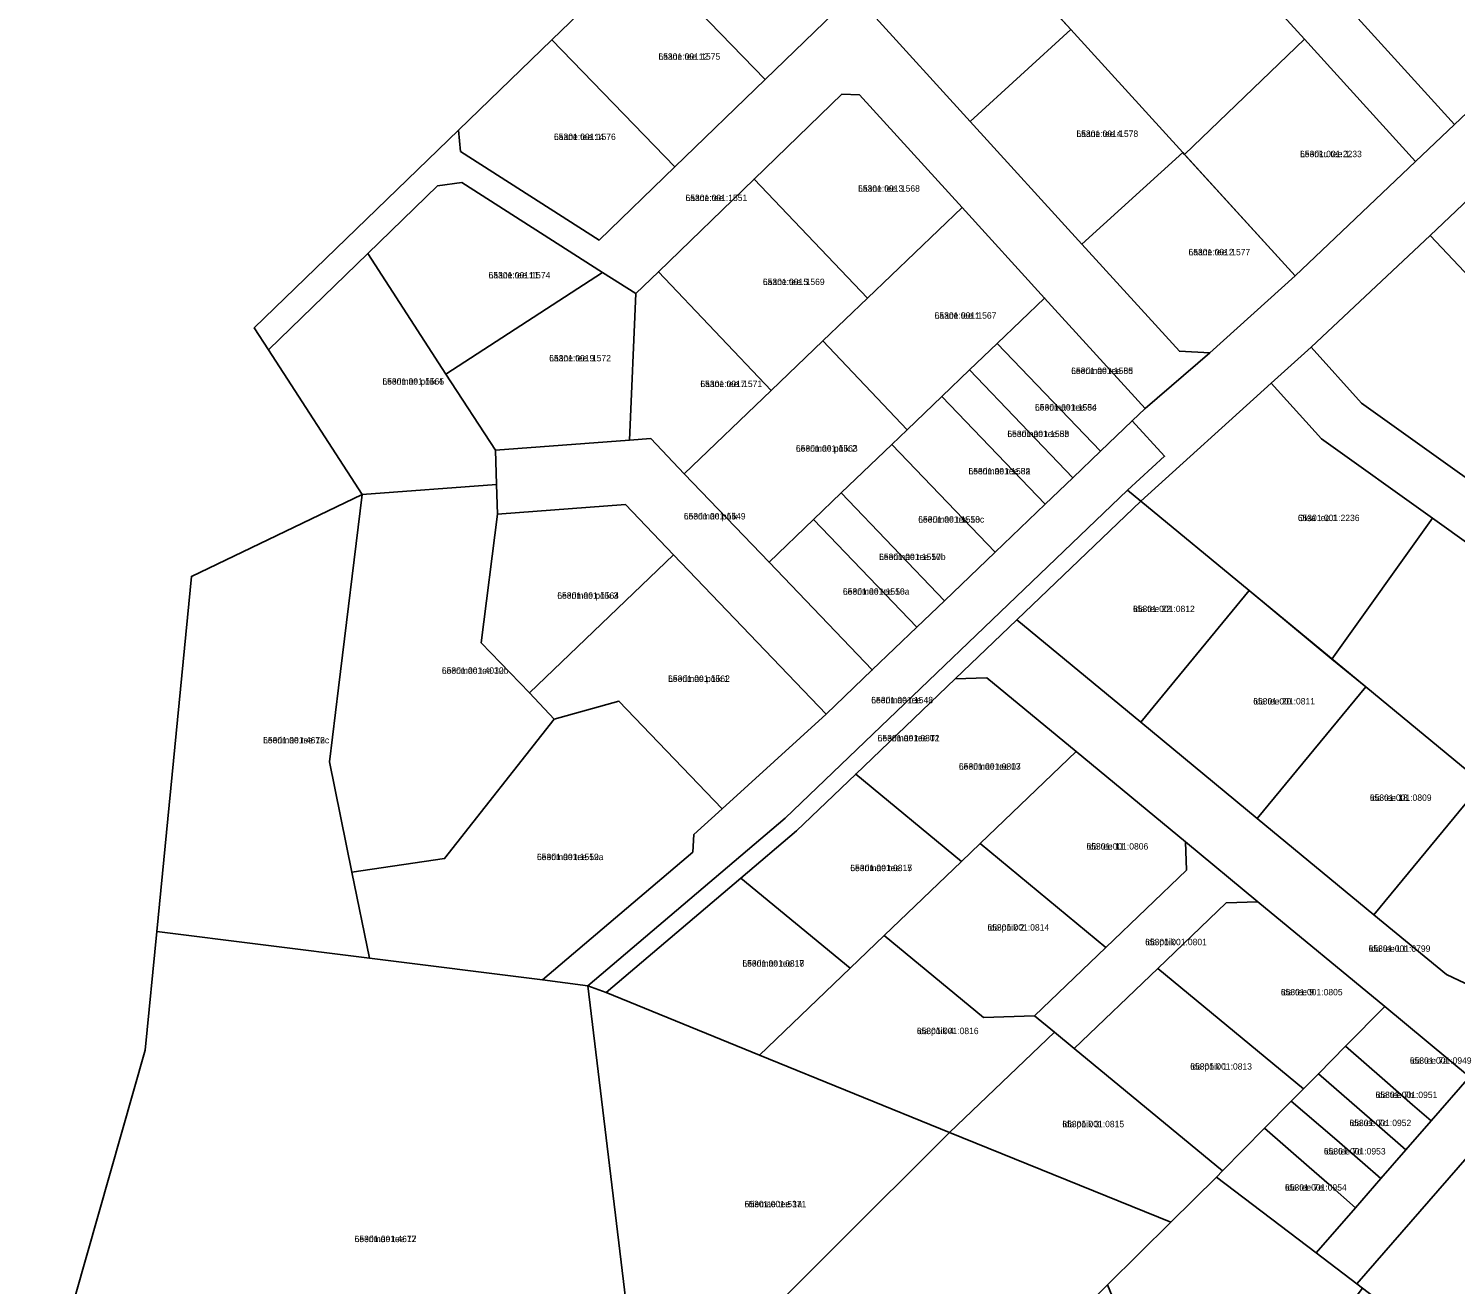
# Model space of a CAD drawing. Extents: x 543236 to 563717, y 6566033 to 6588992.
# Drawn here: x 544925.3 to 545260.3, y 6583719.4 to 6584014.2 of the extents above; entities that cross this region are included whole.
import ezdxf

# ---------------------------------------------------------------- set-up
doc = ezdxf.new("R2010")
doc.units = 0
for name, color, linetype in [('L_AADRESS', 7, 'Continuous'), ('PIIR', 7, 'Continuous'), ('TUNNUS', 7, 'Continuous')]:
    doc.layers.add(name, color=color, linetype=linetype)

msp = doc.modelspace()

# ---------------------------------------------------------------- linework, layer by layer
at = {"layer": 'PIIR'}
for points in [[(545178.33, 6584081.44), (545187.09, 6584071.83), (545210.66, 6584045.94), (545234.23, 6584020.06), (545260.06, 6583991.69), (545250.92, 6583983.02), (545224.81, 6584011.69), (545195.17, 6584044.24), (545169.24, 6584072.71), (545173.77, 6584077.07)], [(545184.39, 6583922.14), (545187.41, 6583925.03), (545202.59, 6583938.1), (545222.62, 6583956.17), (545250.92, 6583983.02), (545260.06, 6583991.69), (545293.45, 6584023.35), (545302.59, 6584032.02), (545335.77, 6584063.49), (545347.4, 6584053.85), (545312.69, 6584020.93), (545303.56, 6584012.25), (545263.51, 6583974.28), (545254.34, 6583965.59), (545226.41, 6583939.39), (545217.05, 6583930.95), (545186.41, 6583903.29), (545183.3, 6583905.86), (545191.99, 6583913.79)], [(545069.35, 6584032.04), (545077.3, 6584039.73), (545091.09, 6584053.08), (545119.05, 6584022.38), (545098.21, 6584002.21)], [(545293.45, 6584023.35), (545260.06, 6583991.69), (545234.23, 6584020.06), (545267.42, 6584051.94)], [(545139.7, 6584047.23), (545170, 6584013.95), (545146.34, 6583992.4), (545123.42, 6584017.57)], [(545167.04, 6584017.21), (545195.17, 6584044.24), (545224.81, 6584011.69), (545196.67, 6583984.66), (545196.26, 6583985.12), (545170, 6584013.95)], [(545048.15, 6584011.52), (545069.35, 6584032.04), (545098.21, 6584002.21), (545077.01, 6583981.7)], [(545307.09, 6583923.8), (545266.41, 6583952.86), (545254.34, 6583965.59), (545263.51, 6583974.28), (545274.79, 6583962.43), (545275.28, 6583962.08), (545307.39, 6583939.01), (545356.24, 6583904.18), (545380.64, 6583938.37), (545371.66, 6583954.62), (545340.53, 6583976.87), (545336.5, 6583979.74), (545314.08, 6583995.73), (545310.09, 6584002.03), (545303.56, 6584012.25), (545312.69, 6584020.93), (545322.94, 6584004.89), (545381.28, 6583963.21), (545395.56, 6583937.53), (545359.17, 6583886.59)], [(545026.21, 6583990.3), (545048.15, 6584011.52), (545077.01, 6583981.7), (545059.28, 6583964.55), (545026.71, 6583985.34)], [(545170, 6584013.95), (545196.26, 6583985.12), (545172.6, 6583963.57), (545146.34, 6583992.4)], [(545224.81, 6584011.69), (545250.92, 6583983.02), (545222.62, 6583956.17), (545196.67, 6583984.66)], [(545095.63, 6583978.85), (545116.21, 6583998.76), (545120.39, 6583998.63), (545144.47, 6583972.18), (545122.23, 6583950.88)], [(545196.26, 6583985.12), (545222.62, 6583956.17), (545202.59, 6583938.1), (545195.5, 6583938.43), (545172.6, 6583963.57)], [(545004.94, 6583961.37), (545021.35, 6583977.25), (545027.04, 6583978.02), (545060.05, 6583956.94), (545023.29, 6583933.09)], [(545073.18, 6583957.12), (545095.63, 6583978.85), (545122.23, 6583950.88), (545111.77, 6583940.86), (545099.66, 6583929.26)], [(545111.77, 6583940.86), (545122.23, 6583950.88), (545144.47, 6583972.18), (545163.83, 6583950.92), (545152.73, 6583940.28), (545146.23, 6583934.06), (545139.73, 6583927.83), (545131.58, 6583920.02)], [(545226.41, 6583939.39), (545254.34, 6583965.59), (545266.41, 6583952.86), (545307.09, 6583923.8), (545285, 6583892.88), (545238.22, 6583926.3)], [(544981.62, 6583938.8), (545004.94, 6583961.37), (545023.29, 6583933.09), (545034.91, 6583915.2), (545035.15, 6583907.17), (545003.65, 6583904.82)], [(545067.85, 6583951.97), (545073.18, 6583957.12), (545099.66, 6583929.26), (545079.25, 6583909.71), (545071.36, 6583917.94), (545066.38, 6583917.57)], [(545023.29, 6583933.09), (545060.05, 6583956.94), (545067.85, 6583951.97), (545066.38, 6583917.57), (545034.91, 6583915.2)], [(545152.73, 6583940.28), (545163.83, 6583950.92), (545187.41, 6583925.03), (545184.39, 6583922.14), (545176.94, 6583915)], [(545079.25, 6583909.71), (545099.66, 6583929.26), (545111.77, 6583940.86), (545131.58, 6583920.02), (545127.97, 6583916.56), (545116.11, 6583905.2), (545109.61, 6583898.97), (545099.14, 6583888.94)], [(545146.23, 6583934.06), (545152.73, 6583940.28), (545176.94, 6583915), (545170.45, 6583908.77)], [(545217.05, 6583930.95), (545226.41, 6583939.39), (545238.22, 6583926.3), (545285, 6583892.88), (545337.08, 6583855.67), (545339.23, 6583858.68), (545345.74, 6583854.03), (545324.81, 6583824.73), (545318.3, 6583829.38), (545329.93, 6583845.66), (545292.33, 6583872.52), (545254.9, 6583899.25), (545228.87, 6583917.86)], [(545139.73, 6583927.83), (545146.23, 6583934.06), (545170.45, 6583908.77), (545163.95, 6583902.54)], [(545231.3, 6583866.21), (545211.86, 6583882.26), (545186.41, 6583903.29), (545217.05, 6583930.95), (545228.87, 6583917.86), (545254.9, 6583899.25)], [(545127.97, 6583916.56), (545131.58, 6583920.02), (545139.73, 6583927.83), (545163.95, 6583902.54), (545152.2, 6583891.27)], [(545045.98, 6583790.92), (545081.22, 6583820.91), (545081.46, 6583824.99), (545088.12, 6583831.05), (545112.55, 6583853.26), (545123.38, 6583863.64), (545133.84, 6583873.67), (545140.34, 6583879.9), (545152.2, 6583891.27), (545163.95, 6583902.54), (545170.45, 6583908.77), (545176.94, 6583915), (545184.39, 6583922.14), (545191.99, 6583913.79), (545183.3, 6583905.86), (545102.91, 6583828.86), (545056.58, 6583789.51)], [(545034.91, 6583915.2), (545066.38, 6583917.57), (545071.36, 6583917.94), (545079.25, 6583909.71), (545099.14, 6583888.94), (545123.38, 6583863.64), (545112.55, 6583853.26), (545076.73, 6583890.65), (545065.43, 6583902.45), (545035.39, 6583900.19), (545035.15, 6583907.17)], [(545116.11, 6583905.2), (545127.97, 6583916.56), (545152.2, 6583891.27), (545140.34, 6583879.9)], [(544998.1, 6583859.46), (545003.65, 6583904.82), (545035.15, 6583907.17), (545035.39, 6583900.19), (545031.59, 6583870.03), (545042.91, 6583858.26), (545048.74, 6583852.1), (545022.99, 6583819.39), (545001.22, 6583816.2), (544995.93, 6583842.09)], [(544955.42, 6583802.27), (544963.54, 6583885.61), (545003.65, 6583904.82), (544998.1, 6583859.46), (544995.93, 6583842.09), (545001.22, 6583816.2), (545005.34, 6583796.01)], [(545056.58, 6583789.51), (545102.91, 6583828.86), (545183.3, 6583905.86), (545186.41, 6583903.29), (545157.32, 6583875.44), (545142.8, 6583861.53), (545119.51, 6583839.22), (545105.59, 6583825.89), (545092.55, 6583814.8), (545060.94, 6583787.95)], [(545109.61, 6583898.97), (545116.11, 6583905.2), (545140.34, 6583879.9), (545133.84, 6583873.67)], [(545035.39, 6583900.19), (545065.43, 6583902.45), (545076.73, 6583890.65), (545042.91, 6583858.26), (545031.59, 6583870.03)], [(545186.41, 6583903.29), (545211.86, 6583882.26), (545186.39, 6583851.42), (545157.32, 6583875.44)], [(545099.14, 6583888.94), (545109.61, 6583898.97), (545133.84, 6583873.67), (545123.38, 6583863.64)], [(545231.3, 6583866.21), (545254.9, 6583899.25), (545292.33, 6583872.52), (545266.84, 6583836.84), (545266.6, 6583837.04), (545239.23, 6583859.65)], [(545042.91, 6583858.26), (545076.73, 6583890.65), (545112.55, 6583853.26), (545088.12, 6583831.05), (545063.91, 6583856.32), (545048.74, 6583852.1)], [(545211.86, 6583882.26), (545239.23, 6583859.65), (545213.76, 6583828.81), (545186.39, 6583851.42)], [(545142.8, 6583861.53), (545157.32, 6583875.44), (545186.39, 6583851.42), (545213.76, 6583828.81), (545241.12, 6583806.2), (545258.15, 6583792.14), (545284.32, 6583779.8), (545285.35, 6583762.76), (545277.86, 6583766.26), (545237.13, 6583719.53), (545227.55, 6583726.81), (545236.8, 6583737.42), (545242.8, 6583744.3), (545248.66, 6583751.03), (545254.56, 6583757.79), (545263.61, 6583768.17), (545243.69, 6583784.63), (545213.92, 6583809.22), (545196.89, 6583823.29), (545171.25, 6583844.47), (545150.27, 6583861.81)], [(545142.8, 6583861.53), (545150.27, 6583861.81), (545171.25, 6583844.47), (545148.71, 6583822.88), (545144.35, 6583818.7), (545119.51, 6583839.22)], [(545239.23, 6583859.65), (545266.6, 6583837.04), (545241.12, 6583806.2), (545213.76, 6583828.81)], [(545001.22, 6583816.2), (545022.99, 6583819.39), (545048.74, 6583852.1), (545063.91, 6583856.32), (545088.12, 6583831.05), (545081.46, 6583824.99), (545081.22, 6583820.91), (545045.98, 6583790.92), (545005.34, 6583796.01)], [(545148.71, 6583822.88), (545171.25, 6583844.47), (545196.89, 6583823.29), (545197.14, 6583816.65), (545178.21, 6583798.52)], [(545092.55, 6583814.8), (545105.59, 6583825.89), (545119.51, 6583839.22), (545144.35, 6583818.7), (545126.17, 6583801.29), (545118.17, 6583793.63)], [(545266.6, 6583837.04), (545266.84, 6583836.84), (545281.6, 6583824.65), (545284.32, 6583779.8), (545258.15, 6583792.14), (545241.12, 6583806.2)], [(545161.48, 6583782.5), (545178.21, 6583798.52), (545197.14, 6583816.65), (545196.89, 6583823.29), (545213.92, 6583809.22), (545206.45, 6583808.95), (545190.43, 6583793.61), (545170.8, 6583774.8), (545166.14, 6583778.65)], [(545126.17, 6583801.29), (545144.35, 6583818.7), (545148.71, 6583822.88), (545178.21, 6583798.52), (545161.48, 6583782.5), (545149.46, 6583782.06)], [(545060.94, 6583787.95), (545092.55, 6583814.8), (545118.17, 6583793.63), (545096.89, 6583773.25)], [(545190.43, 6583793.61), (545206.45, 6583808.95), (545213.92, 6583809.22), (545243.69, 6583784.63), (545234.5, 6583775.32), (545228.11, 6583768.86), (545224.64, 6583765.34)], [(544952.71, 6583774.41), (544955.42, 6583802.27), (545005.34, 6583796.01), (545045.98, 6583790.92), (545056.58, 6583789.51), (545067.62, 6583698.06), (545018.53, 6583682.88), (544931.46, 6583656.42), (544925.31, 6583678.14)], [(545096.89, 6583773.25), (545118.17, 6583793.63), (545126.17, 6583801.29), (545149.46, 6583782.06), (545161.48, 6583782.5), (545166.14, 6583778.65), (545141.51, 6583755.06)], [(545170.8, 6583774.8), (545190.43, 6583793.61), (545224.64, 6583765.34), (545221.75, 6583762.42), (545215.48, 6583756.07), (545205.59, 6583746.06)], [(545141.51, 6583755.06), (545087.4, 6583701.18), (545071.7, 6583685.58), (545067.62, 6583698.06), (545056.58, 6583789.51), (545060.94, 6583787.95), (545096.89, 6583773.25)], [(545234.5, 6583775.32), (545243.69, 6583784.63), (545263.61, 6583768.17), (545254.56, 6583757.79), (545250.22, 6583761.58), (545243.68, 6583767.3)], [(545141.51, 6583755.06), (545166.14, 6583778.65), (545170.8, 6583774.8), (545205.59, 6583746.06), (545204.16, 6583744.59), (545193.44, 6583734)], [(545228.11, 6583768.86), (545234.5, 6583775.32), (545243.68, 6583767.3), (545250.22, 6583761.58), (545254.56, 6583757.79), (545248.66, 6583751.03), (545242.43, 6583756.43), (545237.75, 6583760.5)], [(545221.75, 6583762.42), (545224.64, 6583765.34), (545228.11, 6583768.86), (545237.75, 6583760.5), (545242.43, 6583756.43), (545248.66, 6583751.03), (545242.8, 6583744.3), (545238.45, 6583748.05), (545231.86, 6583753.72)], [(545277.86, 6583766.26), (545285.35, 6583762.76), (545286.89, 6583737.31), (545280.75, 6583729.02), (545260.51, 6583701.71), (545238.43, 6583718.54), (545237.13, 6583719.53)], [(545215.48, 6583756.07), (545221.75, 6583762.42), (545231.86, 6583753.72), (545238.45, 6583748.05), (545242.8, 6583744.3), (545236.8, 6583737.42), (545230.61, 6583742.84), (545225.94, 6583746.92)], [(545124.68, 6583665.46), (545097.13, 6583638.45), (545083.06, 6583683.22), (545089.67, 6583693.89), (545087.4, 6583701.18), (545141.51, 6583755.06), (545193.44, 6583734), (545178.62, 6583719.3), (545143.81, 6583684.42)], [(545204.16, 6583744.59), (545205.59, 6583746.06), (545215.48, 6583756.07), (545225.94, 6583746.92), (545230.61, 6583742.84), (545236.8, 6583737.42), (545227.55, 6583726.81)], [(545204.16, 6583744.59), (545227.55, 6583726.81), (545237.13, 6583719.53), (545238.43, 6583718.54), (545206.42, 6583676.48), (545191.67, 6583687.57), (545178.62, 6583719.3), (545193.44, 6583734)]]:
    msp.add_lwpolyline(points, close=True, dxfattribs=at)
msp.add_lwpolyline([(545123.42, 6584017.57), (545146.34, 6583992.4), (545172.6, 6583963.57), (545195.5, 6583938.43), (545202.59, 6583938.1), (545187.41, 6583925.03), (545163.83, 6583950.92), (545144.47, 6583972.18), (545120.39, 6583998.63), (545116.21, 6583998.76), (545095.63, 6583978.85), (545073.18, 6583957.12), (545067.85, 6583951.97), (545060.05, 6583956.94), (545027.04, 6583978.02), (545021.35, 6583977.25), (545004.94, 6583961.37), (544981.62, 6583938.8), (544978.29, 6583943.93), (545026.21, 6583990.3), (545026.71, 6583985.34), (545059.28, 6583964.55), (545077.01, 6583981.7), (545098.21, 6584002.21), (545119.05, 6584022.38)], dxfattribs=at)

# ---------------------------------------------------------------- texts
at = {"layer": 'L_AADRESS'}
for s, p in [('Lääne tee 12', (545073.18, 6584006.87)), ('Lääne tee 14', (545048.66, 6583988.04)), ('Lääne tee 4', (545171.3, 6583988.76)), ('Leeriku tee 1', (545223.8, 6583984)), ('Lääne tee 3', (545120.05, 6583975.91)), ('Lääne tee', (545079.53, 6583973.71)), ('Lääne tee 2', (545197.61, 6583960.98)), ('Lääne tee 11', (545033.31, 6583955.55)), ('Lääne tee 5', (545097.7, 6583953.99)), ('Lääne tee 1', (545138.02, 6583946.1)), ('Lääne tee 9', (545047.53, 6583936.07)), ('Leerimäe tee 8d', (545170.07, 6583933.12)), ('Leerimäe põik 4', (545008.38, 6583930.62)), ('Lääne tee 7', (545083.02, 6583930.04)), ('Leerimäe tee 8c', (545161.58, 6583924.53)), ('Leerimäe tee 8b', (545155.09, 6583918.3)), ('Leerimäe põik 2', (545105.45, 6583914.9)), ('Leerimäe tee 8a', (545145.96, 6583909.55)), ('Leerimäe põik', (545079.14, 6583898.97)), ('Leerimäe tee 10c', (545134.16, 6583898.23)), ('Otsa tee 1', (545223.27, 6583898.58)), ('Leerimäe tee 10b', (545124.98, 6583889.44)), ('Leerimäe põik 3', (545049.44, 6583880.36)), ('Leerimäe tee 10a', (545116.49, 6583881.31)), ('Ida tee 22', (545184.59, 6583877.23)), ('Leerimäe tee 12b', (545022.34, 6583862.75)), ('Leerimäe põik 1', (545075.45, 6583860.85)), ('Leerimäe tee', (545123.14, 6583855.83)), ('Ida tee 20', (545212.81, 6583855.54)), ('Leerimäe tee 12c', (544980.38, 6583846.41)), ('Leerimäe tee T1', (545124.64, 6583846.9)), ('Leerimäe tee 13', (545143.72, 6583840.25)), ('Ida tee 18', (545240.18, 6583832.92)), ('Leerimäe tee 12a', (545044.67, 6583819.01)), ('Ida tee 11', (545173.67, 6583821.49)), ('Leerimäe tee 15', (545118.22, 6583816.42)), ('Ida põik 2', (545150.41, 6583802.47)), ('Ida põik', (545187.43, 6583799.04)), ('Ida tee L1', (545239.9, 6583797.49)), ('Leerimäe tee 17', (545092.89, 6583794.03)), ('Ida tee 9', (545219.29, 6583787.28)), ('Ida põik 4', (545133.84, 6583778.17)), ('Ida põik 1', (545198.01, 6583769.83)), ('Ida tee 7a', (545249.57, 6583771.21)), ('Ida tee 7b', (545241.53, 6583763.18)), ('Ida põik 3', (545168, 6583756.32)), ('Ida tee 7c', (545235.4, 6583756.58)), ('Ida tee 7d', (545229.39, 6583749.92)), ('Ida tee 7e', (545220.26, 6583741.44)), ('Hiiemäe tee 1a', (545093.39, 6583737.54)), ('Leerimäe tee 12', (545001.86, 6583729.35))]:
    msp.add_text(s, height=1.5, dxfattribs=at).set_placement(p)
at = {"layer": 'TUNNUS'}
for s, p in [('65301:001:1575', (545073.18, 6584006.87)), ('65301:001:1576', (545048.66, 6583988.04)), ('65301:001:1578', (545171.3, 6583988.76)), ('65301:001:2233', (545223.8, 6583984)), ('65301:001:1568', (545120.05, 6583975.91)), ('65301:001:1551', (545079.53, 6583973.71)), ('65301:001:1577', (545197.61, 6583960.98)), ('65301:001:1574', (545033.31, 6583955.55)), ('65301:001:1569', (545097.7, 6583953.99)), ('65301:001:1567', (545138.02, 6583946.1)), ('65301:001:1572', (545047.53, 6583936.07)), ('65301:001:1555', (545170.07, 6583933.12)), ('65301:001:1565', (545008.38, 6583930.62)), ('65301:001:1571', (545083.02, 6583930.04)), ('65301:001:1554', (545161.58, 6583924.53)), ('65301:001:1553', (545155.09, 6583918.3)), ('65301:001:1563', (545105.45, 6583914.9)), ('65301:001:1552', (545145.96, 6583909.55)), ('65301:001:1549', (545079.14, 6583898.97)), ('65301:001:1558', (545134.16, 6583898.23)), ('65301:001:2236', (545223.27, 6583898.58)), ('65301:001:1557', (545124.98, 6583889.44)), ('65301:001:1564', (545049.44, 6583880.36)), ('65301:001:1556', (545116.49, 6583881.31)), ('65301:001:0812', (545184.59, 6583877.23)), ('65301:001:4030', (545022.34, 6583862.75)), ('65301:001:1562', (545075.45, 6583860.85)), ('65301:001:1548', (545123.14, 6583855.83)), ('65301:001:0811', (545212.81, 6583855.54)), ('65301:001:4676', (544980.38, 6583846.41)), ('65301:001:0802', (545124.64, 6583846.9)), ('65301:001:0807', (545143.72, 6583840.25)), ('65301:001:0809', (545240.18, 6583832.92)), ('65301:001:1559', (545044.67, 6583819.01)), ('65301:001:0806', (545173.67, 6583821.49)), ('65301:001:0817', (545118.22, 6583816.42)), ('65301:001:0814', (545150.41, 6583802.47)), ('65301:001:0801', (545187.43, 6583799.04)), ('65301:001:0799', (545239.9, 6583797.49)), ('65301:001:0818', (545092.89, 6583794.03)), ('65301:001:0805', (545219.29, 6583787.28)), ('65301:001:0816', (545133.84, 6583778.17)), ('65301:001:0813', (545198.01, 6583769.83)), ('65301:001:0949', (545249.57, 6583771.21)), ('65301:001:0951', (545241.53, 6583763.18)), ('65301:001:0815', (545168, 6583756.32)), ('65301:001:0952', (545235.4, 6583756.58)), ('65301:001:0953', (545229.39, 6583749.92)), ('65301:001:0954', (545220.26, 6583741.44)), ('65301:001:5371', (545093.39, 6583737.54)), ('65301:001:4677', (545001.86, 6583729.35))]:
    msp.add_text(s, height=1.5, dxfattribs=at).set_placement(p)

doc.saveas('drawing.dxf')
